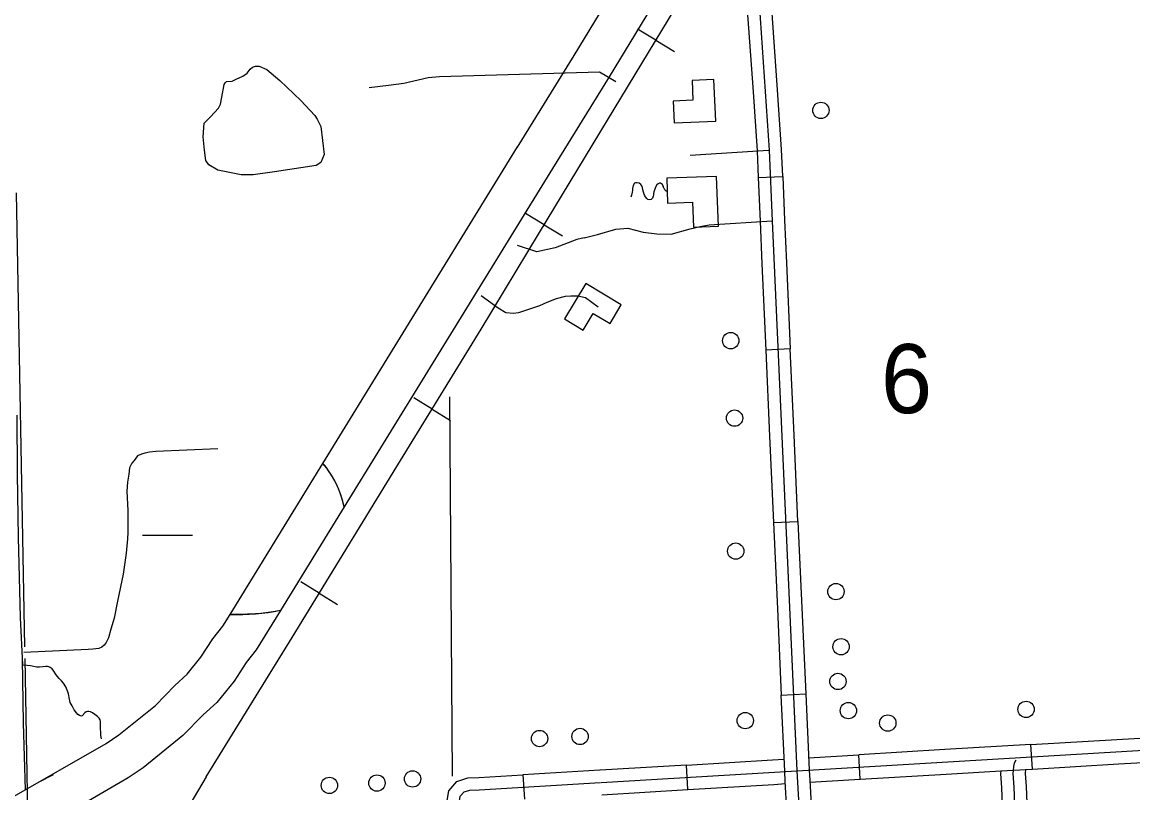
# Model space of a CAD drawing. Extents: x 309348 to 309445, y 336383 to 336484.
# Drawn here: x 309354.217 to 309355.577, y 336402.009 to 336402.952 of the extents above; entities that cross this region are included whole.
import ezdxf

# ---------------------------------------------------------------- set-up
doc = ezdxf.new("R2010")
doc.units = 0
doc.layers.add('R_Annotation', color=7, linetype='Continuous')

msp = doc.modelspace()

# ---------------------------------------------------------------- linework, layer by layer
at = {"layer": 'R_Annotation'}
for p, q in [((309354.9926, 336402.9297), (309354.9699, 336402.9433)), ((309354.9926, 336402.9297), (309355.0152, 336402.916)), ((309355.1179, 336402.7616), (309355.1479, 336402.7629)), ((309354.8557, 336402.7038), (309354.8331, 336402.7175)), ((309354.8557, 336402.7038), (309354.8782, 336402.6901)), ((309355.1572, 336402.5518), (309355.1272, 336402.5505)), ((309354.7186, 336402.4781), (309354.6961, 336402.4919)), ((309354.7186, 336402.4781), (309354.741, 336402.4643)), ((309355.1366, 336402.3394), (309355.1666, 336402.3408)), ((309354.5803, 336402.2531), (309354.5578, 336402.2669)), ((309354.5803, 336402.2531), (309354.6028, 336402.2393)), ((309355.1461, 336402.1284), (309355.1761, 336402.1297)), ((309355.4536, 336402.0378), (309355.4518, 336402.0678)), ((309355.2427, 336402.0254), (309355.2409, 336402.0553)), ((309355.0318, 336402.0128), (309355.03, 336402.0428)), ((309355.4149, 336402.0355), (309355.4536, 336402.0378)), ((309354.8297, 336402.0308), (309354.8315, 336402.0009))]:
    msp.add_line(p, q, dxfattribs=at)
for points in [[(309354.4418, 336402.0282), (309354.5471, 336402.199), (309354.68, 336402.4155), (309354.7788, 336402.576), (309354.85, 336402.6944), (309354.9335, 336402.8317), (309355.0417, 336403.0111), (309355.0903, 336403.0881), (309355.1659, 336403.2109), (309355.2828, 336403.4055), (309355.3801, 336403.5603), (309355.505, 336403.7665), (309355.5504, 336403.8418)], [(309354.4418, 336402.0282), (309354.5471, 336402.199), (309354.68, 336402.4155), (309354.7788, 336402.576), (309354.85, 336402.6944), (309354.9335, 336402.8317), (309355.0417, 336403.0111), (309355.0903, 336403.0881), (309355.1659, 336403.2109), (309355.2828, 336403.4055), (309355.3801, 336403.5603), (309355.505, 336403.7665), (309355.5504, 336403.8418)], [(309354.8233, 336402.7989), (309354.8924, 336402.9109), (309355.0906, 336403.2366)], [(309355.1333, 336403.2106), (309354.9352, 336402.885), (309354.8659, 336402.7728)], [(309355.1152, 336403.0289), (309355.1315, 336402.7951)], [(309355.1414, 336402.8687), (309355.1341, 336402.9741)], [(309355.1041, 336402.972), (309355.1115, 336402.8666)], [(309354.5821, 336402.8241), (309354.5862, 336402.7896), (309354.5821, 336402.78), (309354.5766, 336402.7763), (309354.5256, 336402.7685), (309354.4994, 336402.7648), (309354.4847, 336402.7648), (309354.4562, 336402.7708), (309354.4452, 336402.7772), (309354.4415, 336402.7823), (309354.4397, 336402.7952), (309354.4383, 336402.8112), (309354.4392, 336402.8283), (309354.4472, 336402.8357), (309354.4568, 336402.8463), (309354.4594, 336402.8513), (309354.461, 336402.8598), (309354.4639, 336402.8755), (309354.465, 336402.8773), (309354.4669, 336402.8789), (309354.4738, 336402.8797), (309354.4785, 336402.8821), (309354.4868, 336402.8858), (309354.4921, 336402.8893), (309354.4958, 336402.8941), (309354.4984, 336402.8965), (309354.5024, 336402.8978), (309354.5067, 336402.8978), (309354.5162, 336402.8938), (309354.5319, 336402.8805), (309354.5579, 336402.8558), (309354.5751, 336402.8375), (309354.5778, 336402.833), (309354.5821, 336402.8241)], [(309354.6414, 336402.8719), (309354.6653, 336402.8746), (309354.6838, 336402.8771), (309354.7137, 336402.8838), (309354.7277, 336402.8852), (309354.9234, 336402.8909), (309354.9434, 336402.8792)], [(309355.1115, 336402.8666), (309355.1165, 336402.7943), (309355.1179, 336402.7616)], [(309355.1479, 336402.7629), (309355.1465, 336402.796), (309355.1414, 336402.8687)], [(309354.5849, 336402.4117), (309354.8233, 336402.799)], [(309355.0345, 336402.7889), (309355.1305, 336402.7951)], [(309355.1315, 336402.7951), (309355.1351, 336402.7088), (309355.1653, 336402.0358), (309355.2254, 336400.98), (309355.3345, 336398.9303)], [(309354.8659, 336402.7728), (309354.6108, 336402.3585)], [(309355.0062, 336402.7447), (309355.0058, 336402.7448), (309355.0053, 336402.745), (309355.0048, 336402.7454), (309355.0043, 336402.7458), (309355.004, 336402.746), (309355.0037, 336402.7465), (309355.0034, 336402.7468), (309355.0031, 336402.7473), (309355.0026, 336402.7481), (309355.0023, 336402.7488), (309355.002, 336402.7495), (309355.0017, 336402.7507), (309355.0012, 336402.7518), (309355.0005, 336402.7531), (309354.9995, 336402.754), (309354.9982, 336402.7545), (309354.9968, 336402.7545), (309354.9954, 336402.7539), (309354.9937, 336402.7525), (309354.9921, 336402.7499), (309354.9911, 336402.7474), (309354.9902, 336402.7442), (309354.9898, 336402.742), (309354.9896, 336402.7404), (309354.9893, 336402.7386), (309354.9883, 336402.7363), (309354.9868, 336402.7348), (309354.9848, 336402.7344), (309354.9829, 336402.7349), (309354.9813, 336402.7361), (309354.9797, 336402.7378), (309354.9786, 336402.74), (309354.9775, 336402.7435), (309354.9767, 336402.7465), (309354.9761, 336402.7494), (309354.9755, 336402.7513), (309354.9741, 336402.7532), (309354.9719, 336402.7548), (309354.9697, 336402.7552), (309354.9678, 336402.7551), (309354.9663, 336402.7545), (309354.9646, 336402.7519), (309354.9638, 336402.7483), (309354.9638, 336402.746), (309354.9636, 336402.7437), (309354.9628, 336402.7401), (309354.9617, 336402.7374)], [(309355.1179, 336402.7616), (309355.1201, 336402.7082), (309355.1225, 336402.656)], [(309355.1479, 336402.7629), (309355.1501, 336402.7095), (309355.1524, 336402.6574)], [(309354.2198, 336402.1872), (309354.2095, 336402.743)], [(309354.9049, 336402.6879), (309354.9209, 336402.6919), (309354.9437, 336402.6985), (309354.9583, 336402.6996), (309354.9768, 336402.6946), (309354.9936, 336402.6927), (309355.0111, 336402.6923), (309355.0345, 336402.699), (309355.0467, 336402.7017), (309355.0578, 336402.7039), (309355.1351, 336402.7088)], [(309354.9049, 336402.6879), (309354.8956, 336402.6856), (309354.8692, 336402.6754), (309354.8467, 336402.6707), (309354.8231, 336402.6784)], [(309355.1225, 336402.656), (309355.1272, 336402.5505)], [(309355.1524, 336402.6574), (309355.1572, 336402.5518)], [(309354.9219, 336402.6031), (309354.9065, 336402.6142), (309354.897, 336402.6164), (309354.8886, 336402.6166), (309354.8816, 336402.6159), (309354.8703, 336402.613), (309354.8592, 336402.6088), (309354.8499, 336402.6045), (309354.8354, 336402.5996), (309354.8245, 336402.5961), (309354.8181, 336402.5952), (309354.8087, 336402.596), (309354.7995, 336402.6016), (309354.7788, 336402.6169)], [(309355.1619, 336402.4463), (309355.1572, 336402.5518)], [(309355.1272, 336402.5505), (309355.1319, 336402.445)], [(309354.7397, 336402.4931), (309354.7432, 336402.0293)], [(309354.2101, 336402.4708), (309354.2104, 336402.3988), (309354.2118, 336402.3215), (309354.2139, 336402.2232), (309354.217, 336402.1654)], [(309355.1319, 336402.445), (309355.1366, 336402.3394)], [(309355.1666, 336402.3408), (309355.1619, 336402.4463)], [(309354.4562, 336402.4296), (309354.3803, 336402.4263), (309354.3725, 336402.4254), (309354.3668, 336402.4245), (309354.3628, 336402.4232), (309354.3578, 336402.4209), (309354.3535, 336402.4155), (309354.3507, 336402.4121), (309354.348, 336402.4063), (309354.3472, 336402.3988), (309354.3454, 336402.3887), (309354.3448, 336402.378), (309354.346, 336402.3541), (309354.3459, 336402.3271), (309354.3454, 336402.3195), (309354.3438, 336402.3019), (309354.3401, 336402.2763), (309354.3333, 336402.2433), (309354.3293, 336402.2226), (309354.3251, 336402.2091), (309354.3221, 336402.1986), (309354.3192, 336402.1926), (309354.3168, 336402.1893), (309354.3142, 336402.1869), (309354.3106, 336402.1853), (309354.3029, 336402.1847), (309354.2973, 336402.1841), (309354.2186, 336402.1804)], [(309354.4711, 336402.227), (309354.5849, 336402.4117)], [(309354.6108, 336402.3585), (309354.609, 336402.3666), (309354.6068, 336402.3733), (309354.6039, 336402.3809), (309354.6015, 336402.3866), (309354.5996, 336402.3903), (309354.5953, 336402.3976), (309354.5918, 336402.4027), (309354.5891, 336402.4067), (309354.587, 336402.4094), (309354.5849, 336402.4117)], [(309354.6108, 336402.3585), (309354.5329, 336402.232)], [(309355.1366, 336402.3394), (309355.1414, 336402.2339)], [(309355.1666, 336402.3408), (309355.1713, 336402.2353)], [(309354.4252, 336402.3236), (309354.3638, 336402.3236)], [(309354.2039, 336402.0031), (309354.3195, 336402.0692), (309354.3347, 336402.0796), (309354.3797, 336402.1158), (309354.4034, 336402.1402), (309354.4186, 336402.1539), (309354.4355, 336402.1747), (309354.4502, 336402.1973), (309354.4622, 336402.2125), (309354.4711, 336402.227)], [(309354.5329, 336402.232), (309354.5032, 336402.1838), (309354.4909, 336402.1681), (309354.476, 336402.1452), (309354.455, 336402.1194), (309354.4381, 336402.1041), (309354.4134, 336402.0787), (309354.3646, 336402.0394), (309354.3463, 336402.027), (309354.2287, 336401.9584)], [(309354.5329, 336402.232), (309354.5239, 336402.2304), (309354.5088, 336402.2283), (309354.5022, 336402.2276), (309354.499, 336402.2274), (309354.4924, 336402.2272), (309354.4862, 336402.2269), (309354.4711, 336402.227)], [(309355.1414, 336402.2339), (309355.1461, 336402.1284)], [(309355.1713, 336402.2353), (309355.1761, 336402.1297)], [(309354.2167, 336402.1725), (309354.2178, 336402.0938), (309354.22, 336402.0124)], [(309354.2259, 336401.9459), (309354.224, 336401.9615), (309354.2201, 336402.1733)], [(309354.2718, 336402.1344), (309354.2699, 336402.1384), (309354.2672, 336402.1428), (309354.2645, 336402.1458), (309354.2618, 336402.1486), (309354.2594, 336402.1513), (309354.2572, 336402.1542), (309354.2552, 336402.1578), (309354.2531, 336402.1606), (309354.2508, 336402.1622), (309354.249, 336402.163), (309354.2475, 336402.1635), (309354.2454, 336402.1635), (309354.242, 336402.1628), (309354.2379, 336402.1625), (309354.2344, 336402.1627), (309354.2267, 336402.164), (309354.2228, 336402.1646), (309354.2166, 336402.1649)], [(309354.3136, 336402.0748), (309354.3136, 336402.075), (309354.313, 336402.0791), (309354.3129, 336402.0828), (309354.3123, 336402.0871), (309354.3123, 336402.0942), (309354.3126, 336402.096), (309354.3121, 336402.0981), (309354.3107, 336402.1001), (309354.3087, 336402.1022), (309354.3054, 336402.1047), (309354.3026, 336402.1068), (309354.3002, 336402.1078), (309354.2981, 336402.1083), (309354.2965, 336402.1081), (309354.2949, 336402.1077), (309354.2933, 336402.1068), (309354.29, 336402.103), (309354.289, 336402.1026), (309354.2878, 336402.1029), (309354.2866, 336402.1034), (309354.2847, 336402.1047), (309354.2831, 336402.1065), (309354.2802, 336402.1104), (309354.2776, 336402.1151), (309354.2754, 336402.1192), (309354.2743, 336402.1232), (309354.2732, 336402.1298), (309354.2726, 336402.1323), (309354.2718, 336402.1344)], [(309355.1761, 336402.1297), (309355.1802, 336402.0366), (309355.1809, 336402.0244)], [(309355.151, 336402.0227), (309355.1503, 336402.0351), (309355.1461, 336402.1284)], [(309354.9254, 336402.0215), (309355.1653, 336402.0358), (309355.7066, 336402.0678), (309356.2375, 336402.1009), (309356.3641, 336402.1095)], [(309355.5572, 336402.074), (309355.6627, 336402.0802)], [(309355.3463, 336402.0616), (309355.2409, 336402.0553)], [(309355.4518, 336402.0678), (309355.3463, 336402.0616)], [(309355.4518, 336402.0678), (309355.5572, 336402.074)], [(309355.03, 336402.0428), (309355.1354, 336402.0491)], [(309355.1354, 336402.0491), (309355.1496, 336402.0499)], [(309355.1796, 336402.0517), (309355.2409, 336402.0553)], [(309355.4334, 336402.0487), (309355.4312, 336402.0449), (309355.4304, 336402.0411), (309355.4299, 336402.036), (309355.4297, 336402.0324), (309355.4309, 336402.0155), (309355.4364, 336401.8805)], [(309355.559, 336402.0441), (309355.725, 336402.0531)], [(309354.9239, 336402.0364), (309354.8297, 336402.0308)], [(309355.03, 336402.0428), (309354.9245, 336402.0365)], [(309355.3481, 336402.0316), (309355.4149, 336402.0355)], [(309355.4149, 336402.0355), (309355.4147, 336402.0322), (309355.4159, 336402.0147), (309355.4188, 336401.9432)], [(309355.445, 336402.0373), (309355.4447, 336402.0325), (309355.4459, 336402.0164), (309355.4488, 336401.9445)], [(309355.445, 336402.0373), (309355.4536, 336402.0378)], [(309355.4536, 336402.0378), (309355.559, 336402.0441)], [(309354.2545, 336402.0307), (309354.237, 336402.0218)], [(309354.4418, 336402.0282), (309354.4111, 336401.9767)], [(309354.4233, 336401.958), (309354.7325, 336401.9695), (309354.7392, 336401.9716), (309354.7459, 336401.9756), (309354.7513, 336401.9936), (309354.7531, 336402.0045), (309354.7576, 336402.0098), (309354.7649, 336402.0121), (309354.7763, 336402.0126), (309354.9248, 336402.0215)], [(309354.733, 336401.9845), (309354.7367, 336401.9969), (309354.739, 336402.011), (309354.7489, 336402.0227), (309354.7623, 336402.0271), (309354.7756, 336402.0276), (309354.8297, 336402.0308)], [(309355.157, 336401.9172), (309355.151, 336402.0227)], [(309355.1809, 336402.0244), (309355.1869, 336401.9189)], [(309355.1811, 336402.0217), (309355.2427, 336402.0254)], [(309355.2427, 336402.0254), (309355.3481, 336402.0316)], [(309354.9263, 336402.0065), (309355.0318, 336402.0128)], [(309355.0318, 336402.0128), (309355.1372, 336402.0191)], [(309355.1372, 336402.0191), (309355.1511, 336402.02)]]:
    msp.add_lwpolyline(points, dxfattribs=at)
for points in [[(309355.0659, 336402.8306), (309355.0636, 336402.8814), (309355.0369, 336402.8802), (309355.0379, 336402.8562), (309355.0139, 336402.8551), (309355.0151, 336402.8284)], [(309355.0691, 336402.7019), (309355.067, 336402.763), (309355.0058, 336402.761), (309355.0069, 336402.7304), (309355.0375, 336402.7314), (309355.0385, 336402.7008)], [(309354.9067, 336402.6321), (309354.8805, 336402.5886), (309354.9034, 336402.5748), (309354.9159, 336402.5954), (309354.9364, 336402.583), (309354.9502, 336402.6059)]]:
    msp.add_lwpolyline(points, close=True, dxfattribs=at)
for centre in [(309355.1946, 336402.8438), (309355.0842, 336402.562), (309355.0889, 336402.4672), (309355.0903, 336402.3045), (309355.2131, 336402.255), (309355.2193, 336402.1875), (309355.2155, 336402.145), (309355.2283, 336402.1093), (309355.4459, 336402.1109), (309355.102, 336402.0971), (309355.2766, 336402.0941), (309354.8501, 336402.0752), (309354.8997, 336402.0777), (309354.6946, 336402.0257), (309354.5928, 336402.0178), (309354.651, 336402.0207)]:
    msp.add_circle(centre, 0.01, dxfattribs=at)
for centre, radius, start, end in [((309354.4941, 336402.3344), 0.1192, 11.6704, 40.4177), ((309354.4941, 336402.3344), 0.1192, 11.6704, 40.4177), ((309354.4806, 336402.4956), 0.2687, 267.9853, 281.2348), ((309354.4806, 336402.4956), 0.2687, 267.9853, 281.2348)]:
    msp.add_arc(centre, radius, start, end, dxfattribs=at)

# ---------------------------------------------------------------- texts
msp.add_text('6', height=0.0845, dxfattribs=at).set_placement((309355.2681, 336402.4733))

doc.saveas('drawing.dxf')
